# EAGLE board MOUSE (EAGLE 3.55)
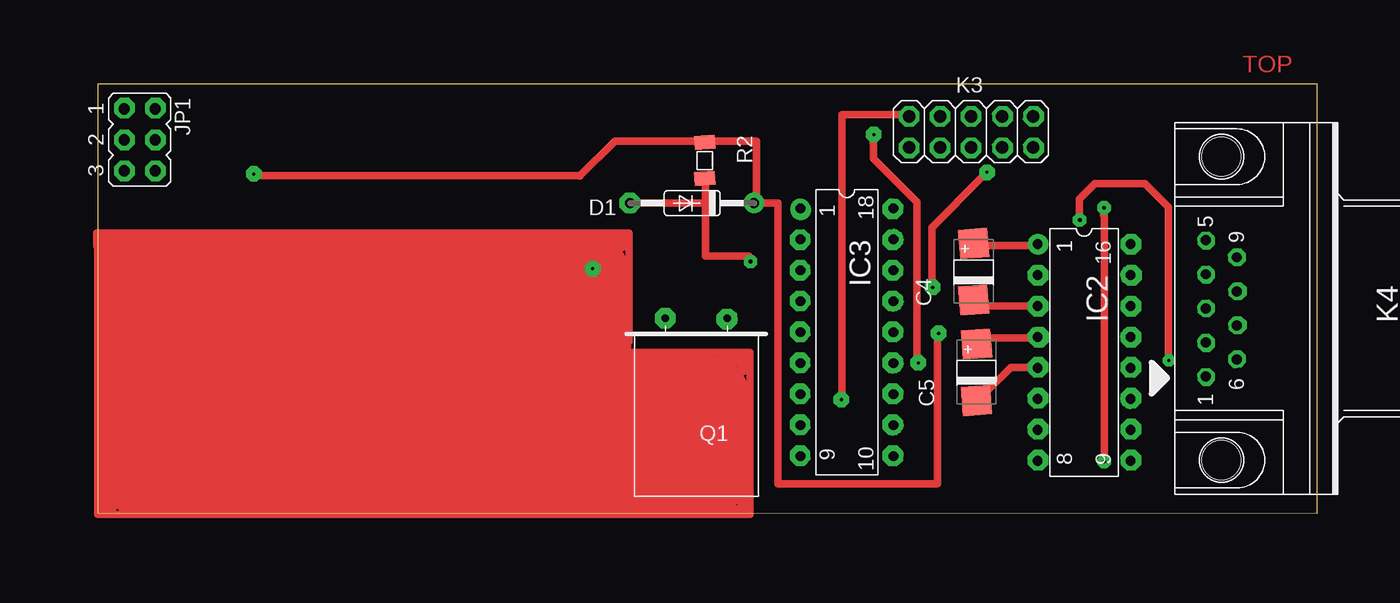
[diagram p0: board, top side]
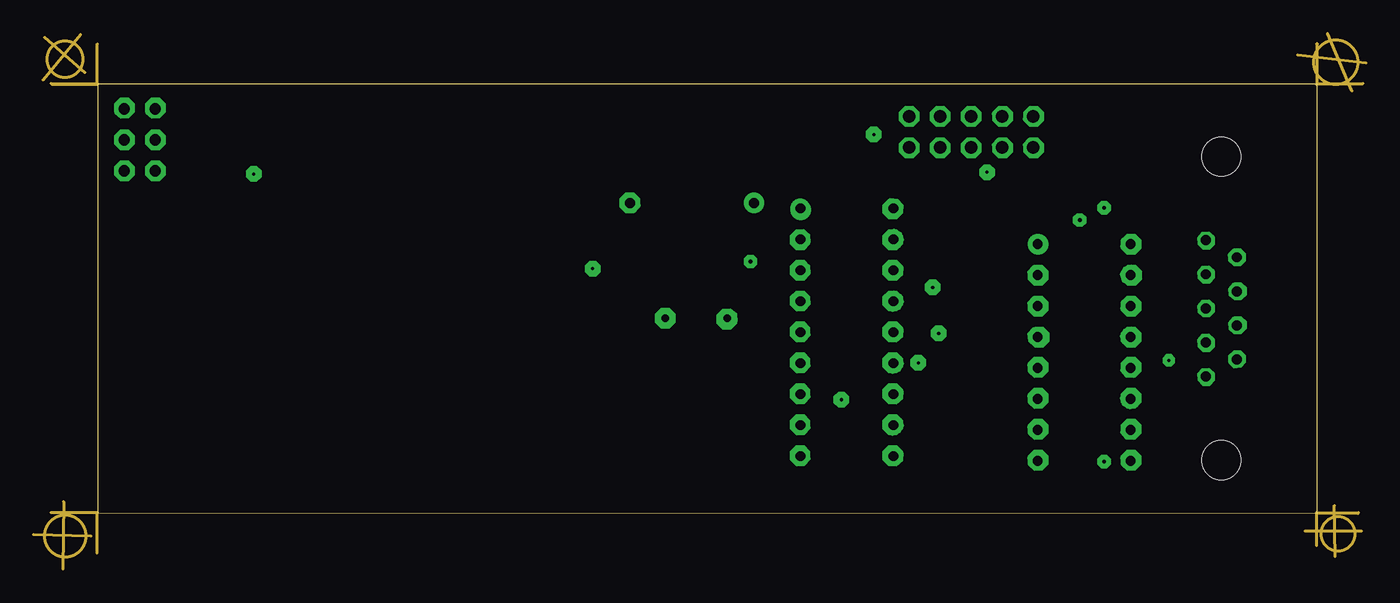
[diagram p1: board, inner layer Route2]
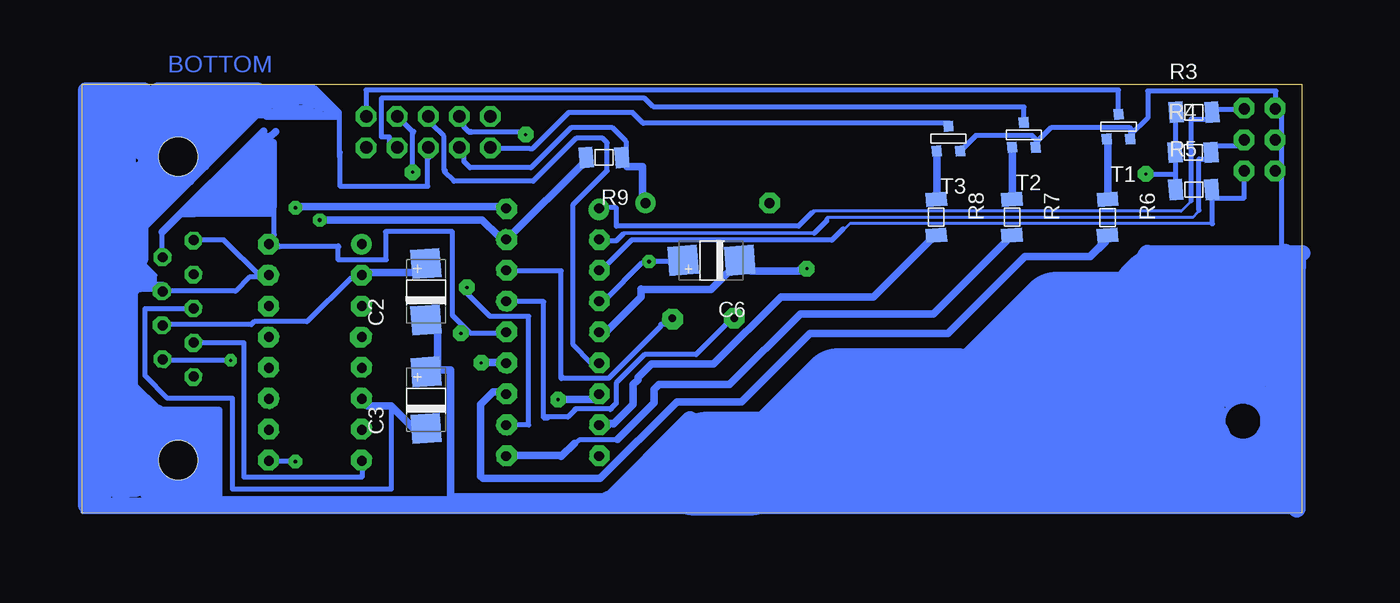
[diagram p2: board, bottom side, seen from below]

Size 99.98 x 35.21 mm. Coordinates in mm from the lower left corner, seen from the top.
Outline: 0,0.06 99.98,0 99.98,35.21 0,35.21 0,0.06
Copper layers used: Top, Route2, Bottom

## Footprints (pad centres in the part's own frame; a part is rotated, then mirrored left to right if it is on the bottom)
32 = smd 2.388 x 2.388 rotated 4.4:  2.337,0 | smd 2.388 x 2.388 rotated 4.3:  -2.311,0
35-10 = drill 0.813 pad 1.6 round:  -5.08,0 | drill 0.813 pad 1.6 octagon:  5.08,0
L16 = drill 0.813 pad 1.6 round:  -8.89,-3.81 | drill 0.813 pad 1.6 octagon:  -6.35,-3.81;  -3.81,-3.81;  -1.27,-3.81;  1.27,-3.81;  3.81,-3.81;  6.35,-3.81;  8.89,-3.81;  8.89,3.81;  6.35,3.81;  3.81,3.81;  1.27,3.81;  -1.27,3.81;  -3.81,3.81;  -6.35,3.81;  -8.89,3.81
L18 = drill 0.813 pad 1.6 round:  -10.16,-3.81 | drill 0.813 pad 1.6 octagon:  -7.62,-3.81;  -5.08,-3.81;  -2.54,-3.81;  0,-3.81;  2.54,-3.81;  5.08,-3.81;  7.62,-3.81;  10.16,-3.81;  10.16,3.81;  7.62,3.81;  5.08,3.81;  2.54,3.81;  0,3.81;  -2.54,3.81;  -5.08,3.81;  -7.62,3.81;  -10.16,3.81
3Q = drill 0.914 pad 1.6 octagon:  -2.54,-1.27;  -2.54,1.27;  0,-1.27;  0,1.27;  2.54,-1.27;  2.54,1.27
05 = drill 1.016 pad 1.575 octagon:  -5.08,-1.27;  -5.08,1.27;  -2.54,-1.27;  -2.54,1.27;  0,-1.27;  0,1.27;  2.54,-1.27;  2.54,1.27;  5.08,-1.27;  5.08,1.27
09M/90 = drill 0.813 pad 1.397 octagon:  5.588,-1.27;  2.794,-1.27;  0,-1.27;  -2.794,-1.27;  -5.588,-1.27;  4.191,1.27;  1.397,1.27;  -1.397,1.27;  -4.191,1.27 | hole 3.2: 12.446,0; -12.446,0
 = drill 0.61 pad 1.6 octagon:  -2.54,-7.62;  2.54,-7.62
06 = smd 1.143 x 1.702 rotated 4.4:  1.473,0 | smd 1.143 x 1.702 rotated 4.3:  -1.473,0
T-23 = smd 0.787 x 0.889 rotated 4.4:  0.991,1.016 | smd 0.787 x 0.889 rotated 4.3:  -0.94,1.016 | smd 0.787 x 0.889 rotated 4.5:  0.025,-1.016

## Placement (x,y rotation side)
C2  10uF  [32]  71.81,18.17 90 bottom
C3  10uF  [32]  71.81,9.27 90 bottom
C4  10uF  [32]  71.82,19.81 90 top
C5  10uF  [32]  72.05,11.57 90 top
C6  10uF  [32]  48.39,20.76 180 bottom
D1  1N4148  [35-10]  48.74,25.45 180 top
IC2  MAX232  [L16]  80.87,13.21 270 top
IC3  16C84 Mouse  [L18]  61.42,14.86 270 top
JP1  [3Q]  3.44,30.64 270 top
K3  Mouse Conector  [05]  71.6,31.3 0 top
K4  Canon  [09M/90]  92.13,16.82 270 top
Q1  11.0592MHz  []  49.09,8.38 180 top
R2  10K  [06]  49.78,28.95 270 top
R3  10K  [06]  8.85,32.91 0 bottom
R4  10K  [06]  8.91,29.62 0 bottom
R5  10K  [06]  8.86,26.56 0 bottom
R6  4K7  [06]  15.93,24.28 270 bottom
R7  4K7  [06]  23.77,24.29 270 bottom
R8  4K7  [06]  29.97,24.29 270 bottom
R9  10K  [06]  57.21,29.19 180 bottom
T1  NPN  [T-23]  15.01,31.73 180 bottom
T2  NPN  [T-23]  22.77,31.04 180 bottom
T3  NPN  [T-23]  28.95,30.74 180 bottom

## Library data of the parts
C2-C6 R2-R9 T1-T3 = SMD
D1 = DIODE
IC2 = MAXIM
IC3 = PIC
JP1 = JUMPS
K3 = PINHEAD
K4 = CONNECT
Q1 = SPECIAL

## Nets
N$1: R6.
N$2: R7.
S$28: C6.
S$161: K3.
S$198: R6.

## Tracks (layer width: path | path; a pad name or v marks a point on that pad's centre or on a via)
0V
  Bottom 0.254: 95.72,18.16 95.72,10.76 93.52,8.56 88.61,8.56 88.61,1.26 69.55,1.26
  Bottom 0.61: 69.72,1.16 69.82,1.06 88.62,1.06 88.82,1.26 88.82,8.46 93.82,8.46 95.72,10.36 95.72,18.16 95.62,18.26
+5V
  Bottom 0.406: 10.35,32.31 10.35,26.99 10.39,26.99 10.39,27.84 12.39,27.84
GND
  Bottom 0.254: 2.09,1.26 69.49,1.26
N$1
  Bottom 0.61: 15.92,30.46 15.92,25.96 15.94,25.95 R6.
N$2
  Bottom 0.61: 23.72,29.66 23.72,25.96 23.77,25.91 R7.
N$3
  Bottom 0.61: 29.92,26.26 29.92,29.46
N$25  (via drill 0.3 pad 1.1)
  other vias: 82.52,25.06
S$1
  Bottom 0.406: 53.15,33.33 22.77,33.33 22.77,32.31
S$2
  Bottom 0.406: 7.62,32.35 9.07,32.35 9.07,25.63
S$3
  Bottom 0.61: 87.06,24.96 85.08,24.96 | 87.06,24.96 87.06,27.31 | 87.06,24.96 90.7,24.96 90.7,25.27 90.83,25.27 90.83,24.59 91.82,24.59 91.82,24.65 84.4,24.65 84.4,24.84 86.81,27.25 86.81,27.43 86.93,27.56 87.24,27.56 87.99,26.82 85.64,26.82 85.39,26.57 85.39,27.37 86.5,27.37 87.06,27.93 87.37,27.93 88.85,26.45 85.33,26.45 85.02,26.14 85.02,27.87 84.96,27.93 86.87,27.93 87.12,28.18 87.55,28.18 89.72,26.01 85.08,26.01 84.65,25.58 84.65,28.92 85.39,29.66 85.39,28.98 84.83,28.42 87.12,28.42 87.24,28.55 87.43,28.55 90.46,25.52 84.71,25.52 84.34,25.15 84.34,28.92 84.9,29.47 84.9,29.72 84.65,29.97 84.65,29.16 85.95,29.16 86.01,29.23 | 86.01,29.23 | 86.01,29.23 84.77,30.46 84.4,30.46 84.34,30.4 84.34,28.98 84.46,28.86 87.31,28.86 87.37,28.92 86.93,28.92 84.96,30.89 84.59,30.89 84.15,31.33
S$4
  Bottom 0.406: 59.36,5.91 59.25,6.01 56.08,6.01
S$5
  Bottom 0.254: 99.97,0.06 99.97,35.17
S$6
  Bottom 0.254: -0.02,0.06 99.95,0.06
S$7
  Bottom 0.406: 84.4,22.71 84.25,22.86 84.25,25.27
S$8  (via drill 0.25 pad 1.27)
  other vias: 40.59,20.08
S$9
  Bottom 0.406: 7.79,29.07 8.43,29.07 8.43,24.86
S$10
  Bottom 0.406: 7.33,23.76 7.37,23.76 7.37,25.84 4.77,25.84 4.77,27.54
S$11
  Bottom 0.254: 37.42,23.41 37.06,23.77 7.42,23.77
S$12
  Bottom 0.61: 76.59,8.82 74.68,8.82 72.89,7.04
S$13
  Bottom 0.61: 30.52,22.36 35.12,17.76 42.72,17.76 48.22,12.26 53.32,12.26 54.42,11.16 54.42,10.96 54.82,10.56 54.82,8.96 56.42,7.36
S$14
  Bottom 0.61: 24.22,22.36 30.22,16.36 41.12,16.36 46.92,10.56 52.72,10.56 53.12,10.16 53.12,9.06 56.12,6.06
S$15
  Bottom 0.61: 60.72,4.66 59.62,5.76
S$16
  Bottom 0.61: 16.12,22.26 17.32,21.06 22.72,21.06 29.02,14.76 40.32,14.76 45.92,9.16 51.22,9.16 57.52,2.86 67.12,2.86 67.32,3.06 67.32,8.96 66.32,9.96 65.62,9.96
S$17
  Bottom 0.61: 55.32,28.46 54.12,28.46
S$18
  Bottom 0.406: 74.82,30.03 74.82,30.89 75.49,30.89 75.49,34.05 53.87,34.05 53.19,33.37
S$19  (via drill 0.25 pad 1.27)
  other vias: 12.79,27.84
S$20
  Bottom 0.406: 1.75,33.16 1.63,33.16 1.63,21.59
S$21
  Bottom 0.406: 64.5,17.42 64.44,17.42 64.44,17.36 62.15,17.36 62.15,7.84 61.78,7.84
S$22
  Bottom 0.406: 93.22,34.46 97.02,30.66 97.02,21.96 94.72,19.66
  Bottom 0.61: 94.32,19.06 94.42,19.06 94.72,18.76 | 94.72,18.76 94.72,18.56 | 94.72,18.76 94.72,19.66 95.22,19.16 95.22,18.46 95.52,18.76 95.52,20.06 95.62,19.96 | 95.62,19.96 95.62,18.36 | 95.62,19.96 95.62,20.46 95.12,19.96 95.12,19.76 96.02,20.66 96.02,10.56
S$23
  Bottom 0.406: 65.86,29.84 65.8,29.91 63.27,29.91
S$24
  Bottom 0.61: 69.78,1.46 69.78,11.76 70.85,11.76 70.85,15.12 70.93,15.12 70.93,15.08 70.81,15.08
S$25  (via drill 0.3 pad 1.1)
  other vias: 53.52,20.66
S$26
  Top 0.61: 39.51,27.65 42.41,30.55 54,30.55 54,26.14
S$27
  Bottom 0.61: 56.96,14.95 54.18,17.73 54.18,18.41
S$28
  Bottom 0.254: 45.98,20.56 45.98,20.66 C6.
S$29
  Bottom 0.406: 28.84,32.01 54,32.01 54.86,32.87 60.11,32.87 63.08,29.91
S$30
  Bottom 0.406: 71.67,29.23 71.67,29.35 71.49,29.35 71.49,29.23 71.67,29.23 | 78.84,29.6 78.84,26.82 71.67,26.82 71.67,29.23
S$31
  Top 0.61: 13.33,27.71 39.53,27.71 39.53,27.67
S$32
  Bottom 0.406: 38.95,24.07 38.95,24.01 39.97,22.99
S$33
  Bottom 0.254: 39.88,24.79 40.07,24.79 40.19,24.67 40.19,24.64 40.03,24.79 39.88,24.79 | 39.88,24.79 9.88,24.79 9.01,25.67
S$34
  Bottom 0.406: 83.84,32.56 86.38,32.56
S$35
  Bottom 0.406: 68.15,31.33 68.09,31.27 64.01,31.27
S$36
  Bottom 0.406: 68.7,31.95 68.7,31.7 68.27,31.27
S$37  (via drill 0.25 pad 1.68)
  Top 0.61: 53.41,21.1 49.83,21.1 49.83,25.46 | 49.83,27.06 49.83,25.46 | 49.83,25.46 44.36,25.46 44.36,25.49 44.26,25.49
  other vias: 43.61,25.46
S$38
  Bottom 0.406: 56.22,23.56 41.27,23.56 40.16,24.67
S$39
  Top 0.61: 65.74,32.69 61.02,32.69 61.02,9.93
S$40
  Bottom 0.406: 37.6,23.35 38.53,22.42 54.99,22.42
S$41  (via drill 0.25 pad 1.68)
  other vias: 65.18,24.96
S$42  (via drill 0.25 pad 1.68)
  other vias: 65.18,22.43
S$43  (via drill 0.25 pad 1.68)
  other vias: 57.64,24.9
S$44  (via drill 0.25 pad 1.68)
  other vias: 57.58,7.29
S$45  (via drill 0.25 pad 1.27)
  other vias: 68.95,14.77
S$46
  Bottom 6.452: 11.67,9.2 28.72,9.2 28.72,5.62 8.95,5.62 8.95,5.12 9.56,5.12 9.56,10.32
S$47
  Bottom 1.778: 86.32,34.11 98.61,34.11 98.55,34.05 98.55,1.66 96.88,3.33 96.88,32.44 97.38,32.93 97.69,32.93 96.02,31.27 93.55,31.27 93.24,31.57 92.68,31.57 92.81,31.7 92.81,32.13 92.5,32.44 89.1,32.44 89.04,32.5 87.99,32.5 86.63,33.86 85.7,33.86 89.59,29.97 89.72,29.97 90.64,30.89 90.64,31.33 90.77,31.45 | 90.77,31.45 91.26,31.45 | 90.77,31.45 90.02,31.45 90.33,31.76 92,31.76 92.19,31.95 93.55,31.95 94.04,31.45 94.04,30.71 94.41,30.34 94.6,30.34 94.97,29.97 95.15,29.97 94.91,29.72 94.6,29.72 94.6,29.23 94.47,29.1 94.47,28.11 94.54,28.18 94.97,28.18 94.72,27.93 94.23,27.93 93.92,27.62 | 93.92,27.62 | 93.92,27.62 93.55,27.25 93.42,27.25 93.3,27.12 93.05,27.12 93.36,26.82 93.36,26.69 95.46,24.59 95.46,20.95 95.71,21.19 95.71,27.25 95.4,26.94 95.03,26.94 96.33,25.64 96.33,6.3 96.82,5.8 96.82,1.85 96.45,2.22 95.65,2.22 95.46,2.41 95.46,7.54 95.22,7.29 94.29,7.29 94.17,7.16 92.99,7.16 93.92,8.09 95.15,8.09 93.86,6.79 90.95,6.79 90.77,6.61 90.77,6.55 89.84,5.62 89.84,5.37 89.65,5.19 89.65,3.09 89.84,3.27 90.02,3.27 90.21,3.09 90.21,2.65 90.46,2.41 90.77,2.41 90.83,2.34 91.2,2.34 91.08,2.22 91.08,1.73 91.32,1.97 91.75,1.97 91.88,1.85 94.47,1.85 94.23,2.1 93.05,2.1 93.86,2.9 94.04,2.9 94.47,3.33 94.47,3.77 94.54,3.83 94.54,5.12 94.17,5.5 94.17,5.56 93.92,5.8 93.92,5.99 93.42,6.48 93.18,6.48
S$48
  Bottom 1.27: 1.37,21.48 1.37,0.66 89.72,0.66 89.72,8 | 89.72,8 89.72,8.12 | 89.72,8 94.29,8 94.29,8.36 96.94,11.01 96.94,21.96 96.22,22.69 96.22,29.31 97.3,30.39 97.3,23.41 97.66,23.05 97.66,30.87 93.81,34.72 85.62,34.72 86.35,34 92.6,34 95.85,30.75 95.85,33.76 94.89,34.72 99.71,34.72 99.71,0.66 55.77,0.66 54.45,1.98 2.33,1.98 2.33,21.24 2.21,21.36 12.32,21.36 | 12.32,21.36 12.44,21.24 | 12.32,21.36 -0.08,21.36
S$49
  Bottom 0.406: 51.45,20.69 53.06,20.69 53.11,20.65
S$50
  Bottom 0.254: 85.32,31.16 85.3,31.16 85.3,31.14 93.42,23.02
  Bottom 0.406: 85.22,31.26 85.22,31.24 85.3,31.16
S$51  (via drill 0.25 pad 1.68)
  other vias: 66.54,29.97
S$52
  Bottom 0.406: 60.7,11.24 60.55,11.09 56.84,11.09 52.54,15.38
S$53
  Bottom 0.406: 76.72,33.12 76.72,34.73 15.03,34.73 15.03,32.9 15.07,32.9
S$54
  Bottom 0.61: 93.42,23.06 85.12,31.36
S$55
  Bottom 0.406: 57.06,17.59 57.11,17.63 | 53.91,20.56 54.08,20.56 57.06,17.59 | 57.06,17.59
S$56  (via drill 0.25 pad 1.68)
  other vias: 74.2,29.97
S$57  (via drill 0.25 pad 1.68)
  other vias: 69.07,29.97
S$58  (via drill 0.25 pad 1.68)
  other vias: 71.61,29.97
S$59
  Bottom 0.305: 39.85,23.05 39.91,22.99 55.62,22.99
S$60  (via drill 0.25 pad 1.68)
  other vias: 57.58,19.96
S$61
  Bottom 0.254: 8.47,24.76 8.95,24.28 38.92,24.28 39.01,24.19 39.01,24.07
S$62
  Route2 0.254: -0.02,35.2 -3.75,35.2 -3.81,35.26 -0.02,35.26 -0.02,38.51
S$63
  Route2 0.254: -4.47,35.57 -1.4,39.3
S$64
  Route2 0.254: -1.04,36.17 -4.35,39.06
S$65
  Route2 0.254: 99.95,35.2 99.95,38.51 100.01,38.51 100.01,35.26 103.74,35.26
S$66
  Route2 0.254: 100.85,39.36 102.84,34.66 102.78,34.84
S$67
  Route2 0.254: 98.38,37.61 103.98,36.95
S$68
  Route2 0.254: 99.95,-2.65 99.95,0.06 103.38,0.06 103.32,0
S$69
  Route2 0.254: 98.98,-1.45 103.62,-1.45
S$70
  Route2 0.254: 101.45,-3.55 101.39,0.66
S$71
  Route2 0.254: -0.08,0.06 -0.02,0.06 | -0.08,0.06 -3.81,0.06 | -0.08,0.06 -0.08,-3.25
S$72
  Route2 0.254: -2.78,0.96 -2.84,-4.58
S$73
  Route2 0.254: -0.56,-1.87 -5.25,-1.75
S$74
  Bottom 0.61: 92.82,34.26 96.72,30.36 96.72,22.06 94.22,19.56
S$75
  Bottom 0.61: 54.02,18.36 48.42,18.36 47.12,19.66
S$76  (via drill 0.25 pad 1.68)
  other vias: 77.11,22.06
S$77
  Bottom 0.406: 57.06,22.35 56.21,22.35 55.66,22.9
S$78
  Bottom 6.452: 30.08,6.36 30.82,6.36 30.82,5.25 43.18,5.25 43.18,4.75 47.14,4.75 47.14,3.39 49.73,3.39 49.73,3.02 45.28,3.02 37.99,10.32 28.23,10.32 28.1,10.19 26.5,10.19 20.07,16.62 12.28,16.62 12.28,18.1 11.91,18.47 3.01,18.47 3.01,13.65 15,13.65 16.11,12.54 15,12.54 12.28,9.82 33.42,9.82 36.26,6.98 41.2,6.98 43.31,4.88 48.99,4.88 48.74,5.12 28.6,5.12
S$79
  Bottom 1.422: 50.72,6.98 50.17,7.54 50.17,7.66 56.9,0.92 57.09,0.92 56.9,1.11 54.24,1.11 53.19,2.16 53.19,3.27 53.75,2.71 53.75,2.65
S$80
  Bottom 1.422: 12.65,20.82 12.78,20.95 12.78,21.13 12.65,21.25 12.65,21.32 12.53,21.19 0.48,21.19 0.36,21.07 0.36,20.27 0.42,20.2 0.42,0.37 2.83,2.78 2.95,2.78 5.36,5.19 5.67,5.19 6.23,4.63 6.23,2.84 5.61,3.46 5.61,5.5 4.81,4.69 4.81,2.41 4.62,2.59 4.25,2.59 4.62,2.96 4.62,5.31 4.5,5.43 3.82,5.43 3.38,5.87 3.2,5.87 3.08,5.99 3.08,6.36 2.89,6.55 | 2.89,6.55 2.89,6.73 | 2.89,6.55 2.89,5.06 3.01,4.94 3.01,4.14 3.08,4.2 3.45,4.2 2.7,4.94 2.7,8.28 2.77,8.34 2.77,8.83 2.89,8.96 3.01,8.96 3.26,9.2 3.26,9.33 3.38,9.45 3.63,9.45 3.82,9.64 4.31,9.64 4.13,9.82 3.45,9.82 3.51,9.88 5.98,9.88 6.04,9.82 6.04,9.39
S$81
  Bottom 1.016: 91.26,27.37 84.28,34.36 | 91.26,27.37 95.28,23.36 95.34,23.36 | 91.82,27.19 91.88,27.25 91.94,27.25 91.82,27.37 91.26,27.37 | 91.26,27.37 90.02,28.61 90.02,29.35 90.09,29.35
S$82
  Top 0.61: -0.08,21.93 -0.08,22.98 43.55,22.98 43.55,14.09 43.43,14.09 43.43,13.22 53.5,13.22 53.5,-0.07 -0.01,-0.07 -0.01,22.86
S$83
  Top 6.452: 6.54,16.93 3.2,16.93 3.2,19.52 40.34,19.52 40.34,19.77 40.28,19.77 40.28,9.7 50.17,9.7 50.17,3.02 3.38,3.02 3.38,14.58 | 3.38,14.58 3.38,14.77 | 3.38,14.58 36.45,14.58 36.45,6.98 45.28,6.98 45.28,7.23 8.82,7.23 8.82,9.08 8.2,9.08 8.2,9.7 35.4,9.7
S$84
  Top 1.016: 2.83,22 2.83,22.49 0.67,22.49 0.67,21.62 0.54,21.62 0.54,0.43 1.04,0.43
S$85
  Top 1.016: 40.46,21.87 40.46,22.37 42.81,22.37 42.81,22 43,22
S$86
  Top 1.016: 51.22,12.42 51.22,12.54 52.95,12.54 52.95,11.86
S$87
  Top 1.016: 52.95,3.02 52.95,0.49 53.01,0.49 53.01,0.18 52.27,0.18
S$88
  Bottom 0.61: 45.15,19.88 41.19,19.88 41.19,19.97
S$89  (via drill 0.25 pad 1.68)
  other vias: 57.58,17.42
S$90
  Bottom 0.61: 65.8,12.42 65.83,12.45 65.8,12.45 65.86,12.39 65.86,12.36 65.89,12.39 66.85,12.39
S$91  (via drill 0.25 pad 1.68)
  other vias: 65.18,12.36
S$92
  Bottom 0.406: 68.46,18.04 66.57,16.16 63.45,16.16
S$93  (via drill 0.25 pad 1.68)
  other vias: 74.2,32.56
S$94  (via drill 0.25 pad 1.68)
  other vias: 71.61,32.56
S$95  (via drill 0.25 pad 1.68)
  other vias: 69.07,32.56
S$96  (via drill 0.25 pad 1.68)
  other vias: 66.54,32.56
S$97  (via drill 0.25 pad 1.68)
  other vias: 76.74,29.97
S$98  (via drill 0.25 pad 1.68)
  other vias: 77.11,16.99
S$99
  Bottom 0.406: 84.03,33.49 84.83,33.49 | 84.03,33.49 82.42,33.49 | 84.03,33.49 83.78,33.74 81.87,33.74 81.43,33.3 82.92,33.3 83.47,33.86 81.74,33.86 81.74,33.8 81.19,33.24 84.15,33.24 84.22,33.3 84.22,33.49 83.54,34.17 81.62,34.17 80.45,33 84.52,33 84.65,32.87 84.65,33.49 83.72,34.42 81.13,34.42 81.13,34.17 79.7,32.75 84.71,32.75 84.9,32.93 84.9,34.48 85.08,34.66 81.19,34.66 81.06,34.54 81,34.54 78.96,32.5 84.9,32.5 85.27,32.87 85.27,34.79 85.02,35.03 85.02,34.97 84.96,34.91 80.94,34.91 78.9,32.87 78.9,29.29
S$100
  Bottom 0.406: 68.7,29.53 68.7,28.86 68.21,28.36 63.2,28.36 59.93,31.64 56.53,31.64 55.42,30.52 55.42,29.84
S$101  (via drill 0.25 pad 1.68)
  other vias: 76.74,32.56
S$102
  Bottom 0.406: 72.78,31.33 72.91,31.2 72.91,28.42
S$103
  Bottom 0.61: 64.78,22.86 59.06,28.58
S$104
  Bottom 0.406: 56.72,8.52 56.22,9.02 56.22,10.69 53.87,13.03 49.67,13.03 46.95,15.75 46.89,15.75 46.83,15.69
S$105
  Bottom 0.406: 64.5,19.96 64.56,19.96 64.56,19.89 60.73,19.89 60.73,11.06
S$106
  Bottom 0.406: 75.13,23.11 69.63,23.11 69.63,16.25 68.15,14.77 65.86,14.77 65.86,14.64
S$107  (via drill 0.25 pad 1.27)
  other vias: 67.28,12.36
S$108  (via drill 0.25 pad 1.68)
  other vias: 65.18,9.82
S$109
  Bottom 0.406: 63.39,16.16 63.39,7.26 64.66,7.26
S$110
  Bottom 0.61: 60.64,4.76 64.36,4.76
S$111  (via drill 0.25 pad 1.68)
  other vias: 57.58,4.75
S$112
  Bottom 0.61: 56.85,7.25 56.7,7.4 56.38,7.4
S$113  (via drill 0.25 pad 1.27)
  other vias: 60.98,9.33
S$114
  Bottom 0.406: 70.31,28.05 69.51,27.25 63.02,27.25 59.5,30.77 57.33,30.77 56.96,30.4 56.96,28.11 59.74,25.33 59.74,13.84 58.26,12.36
S$115  (via drill 0.25 pad 1.68)
  other vias: 77.17,14.46
S$116
  Bottom 0.61: 65.8,25.05 65.8,25.15 82.08,25.15
S$117
  Bottom 0.406: 56.98,20.14 56.98,20.39 54.98,22.39
S$118  (via drill 0.25 pad 1.68)
  other vias: 57.58,22.43
S$119
  Bottom 0.406: 57.02,25.07 56.21,25.07 56.21,23.54
S$120
  Top 0.61: 72.89,21.95 76.41,21.95
S$121
  Bottom 0.61: 54.04,28.44 54.04,25.97 54,25.93
S$122  (via drill 0.25 pad 1.68)
  other vias: 77.11,11.98
S$123
  Bottom 0.406: 90.27,14.02 90.27,13.93 90.3,13.93 90.3,14.02 | 90.3,14.02 90.27,14.02 | 90.43,14.02 90.46,14.05 | 90.33,14.02 90.3,14.02 | 90.33,14.02 90.27,14.02 | 90.33,14.02 90.43,14.02 | 90.33,14.02 90.36,14.02 90.36,13.99 | 90.43,14.02 90.4,13.99 90.36,13.99 | 90.36,13.99 86.72,13.99 86.72,2.96 77.05,2.96 77.05,3.73
S$124
  Bottom 0.61: 76.55,19.69 76.55,19.74 72.61,19.74
S$125
  Top 0.61: 76.41,16.93 76.34,17.01 72.64,17.01
S$126
  Top 0.61: 76.55,14.39 76.54,14.38 72.95,14.38
S$127
  Top 0.61: 76.48,11.97 74.85,11.97 72.92,10.04
S$128  (via drill 0.25 pad 1.68)
  other vias: 77.11,9.45
S$129  (via drill 0.25 pad 1.68)
  other vias: 77.11,6.92
S$130  (via drill 0.25 pad 1.68)
  other vias: 84.71,22.06
S$131  (via drill 0.25 pad 1.68)
  other vias: 84.77,19.52
S$132  (via drill 0.25 pad 1.68)
  other vias: 84.71,6.92
S$133  (via drill 0.25 pad 1.68)
  other vias: 84.71,9.45
S$134  (via drill 0.25 pad 1.68)
  other vias: 84.71,11.98
S$135  (via drill 0.25 pad 1.68)
  other vias: 84.71,14.46
S$136  (via drill 0.25 pad 1.68)
  other vias: 84.71,16.99
S$137
  Bottom 0.406: 92.9,18.23 87.43,18.23 86.29,19.37 85.33,19.37 88.39,22.43 90.43,22.43
S$138
  Bottom 0.406: 84.06,22.09 83.85,21.87 78.96,21.87
S$139
  Bottom 0.61: 80.01,24.07 67.19,24.07 65.86,22.74
S$140  (via drill 0.25 pad 1.42)
  other vias: 90.89,19.59
S$141
  Bottom 0.406: 91.35,16.8 94.85,16.8 94.85,11.3 92.99,9.45 87.68,9.45 87.68,1.97 74.64,1.97 74.64,8.46
S$142  (via drill 0.25 pad 1.68)
  other vias: 77.11,19.52
S$143  (via drill 0.25 pad 1.42)
  other vias: 90.89,11.18
S$144  (via drill 0.25 pad 1.42)
  other vias: 93.42,21.01
S$145
  Bottom 0.406: 93.05,15.32 93.05,15.48 86.13,15.48 85.88,15.72 81.56,15.72 78.01,19.28 77.7,19.28
S$146
  Bottom 0.406: 94.07,19.55 94.04,19.52 94.04,18.35 95.34,18.35
S$147
  Bottom 0.406: 93.42,21.53 93.42,22.95
S$148  (via drill 0.25 pad 1.68)
  Top 0.61: 68.83,14.02 68.83,2.41 55.79,2.41 55.79,25.46 54.68,25.46 54.61,25.46
  other vias: 53.81,25.46
S$149
  Bottom 0.406: 27.75,29.97 26.73,30.99 22.13,30.99 21.75,30.61 21.75,30.44 20.56,31.63 14.09,31.63 14.01,31.54 14.01,31.07 12.64,32.43 12.64,34.65 2.14,34.65 2.14,33.84 2.26,33.84
S$150  (via drill 0.25 pad 1.68)
  other vias: 2.21,30.65
S$151  (via drill 0.25 pad 1.68)
  other vias: 2.21,28.11
S$152
  Bottom 0.406: 5.24,33.12 7.07,33.12
S$153
  Bottom 0.406: 4.99,30.14 7.07,30.14
S$154
  Bottom 0.406: 94.78,18.69 94.69,18.78 93.39,18.78
S$155
  Top 0.61: 82.46,24.48 82.55,24.39 82.55,4.74
S$156  (via drill 0.25 pad 1.27)
  other vias: 63.64,31.08
S$157  (via drill 0.25 pad 1.68)
  other vias: 65.18,4.75
S$158  (via drill 0.3 pad 1.1)
  other vias: 82.52,4.26
S$159  (via drill 0.25 pad 1.42)
  other vias: 93.48,18.23
S$160
  Top 0.61: 63.57,30.35 63.57,30.48 63.61,30.52 63.61,29.12 67.19,25.54 67.19,12.95
S$162  (via drill 0.25 pad 1.27)
  other vias: 68.46,18.54
S$163  (via drill 0.25 pad 1.68)
  other vias: 65.18,19.96
S$164  (via drill 0.25 pad 1.68)
  other vias: 65.18,17.42
S$165  (via drill 0.25 pad 1.68)
  other vias: 65.18,14.89
S$166  (via drill 0.25 pad 1.68)
  other vias: 57.58,14.89
S$167  (via drill 0.25 pad 1.68)
  other vias: 57.58,12.36
S$168  (via drill 0.25 pad 1.68)
  other vias: 51.59,15.94
S$169  (via drill 0.25 pad 1.68)
  other vias: 46.52,16
S$170  (via drill 0.25 pad 1.42)
  other vias: 90.89,22.37
S$171
  Bottom 0.406: 72.91,31.33 73.65,32.07
S$172
  Bottom 0.406: 75.07,23.02 75.07,20.79 78.99,20.79 78.99,21.93
S$173  (via drill 0.25 pad 1.42)
  other vias: 90.89,16.8
S$174
  Bottom 0.406: 52.58,15.51 51.83,15.51 51.65,15.32
S$175  (via drill 0.25 pad 1.42)
  other vias: 93.48,15.45
S$176
  Bottom 0.406: 62.15,7.91 60.18,7.91 59.56,8.52
S$177
  Bottom 0.406: 56.56,8.65 56.65,8.55 59.59,8.55
S$178
  Bottom 0.406: 71.36,31.95 71.36,32.07 71.3,32.13 71.3,32.07
S$179
  Bottom 0.406: 71.3,31.98 71.3,32.04 71.33,32.07 71.33,31.91 70.34,30.93 70.34,28.21 70.22,28.08
S$180  (via drill 0.25 pad 1.42)
  other vias: 93.42,12.66
S$181  (via drill 0.25 pad 1.42)
  other vias: 90.89,13.96
S$182
  Bottom 0.406: 92.87,12.63 92.87,12.54 88.17,12.54 88.17,12.51 88.2,12.51
S$183  (via drill 0.25 pad 1.68)
  other vias: 84.71,4.38
S$184
  Bottom 0.406: 82.86,4.26 84.18,4.26
S$186  (via drill 0.25 pad 1.68)
  other vias: 77.11,4.38
S$187  (via drill 0.25 pad 1.68)
  other vias: 65.18,7.29
S$188
  Bottom 0.61: 60.55,9.33 60.52,9.36 57.8,9.36
S$189  (via drill 0.25 pad 1.68)
  other vias: 57.58,9.82
S$190  (via drill 0.25 pad 1.68)
  other vias: 2.21,33.24
S$191  (via drill 0.25 pad 1.68)
  other vias: 4.74,33.24
S$192  (via drill 0.25 pad 1.68)
  other vias: 4.74,30.65
S$193  (via drill 0.25 pad 1.68)
  other vias: 4.74,28.11
S$194  (via drill 0.25 pad 1.27)
  other vias: 72.91,27.99
S$195
  Top 0.61: 68.38,19.16 68.38,23.46 72.51,27.58
S$196
  Bottom 0.61: 2.12,1.36 69.62,1.36
S$197  (via drill 0.3 pad 1.1)
  other vias: 80.52,24.06
S$198
  Bottom 0.254: 15.94,22.81 17.76,20.98
S$199
  Top 0.61: 80.51,24.61 80.51,25.8 81.74,27.03 85.87,27.03 87.78,25.12 87.78,13.12
S$200  (via drill 0.25 pad 1.02)
  other vias: 87.82,12.56
(copper drawn outside any net)
  shapes: Bottom circle x1, Route2 circle x4

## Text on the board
Top: TOP
Bottom: BOTTOM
